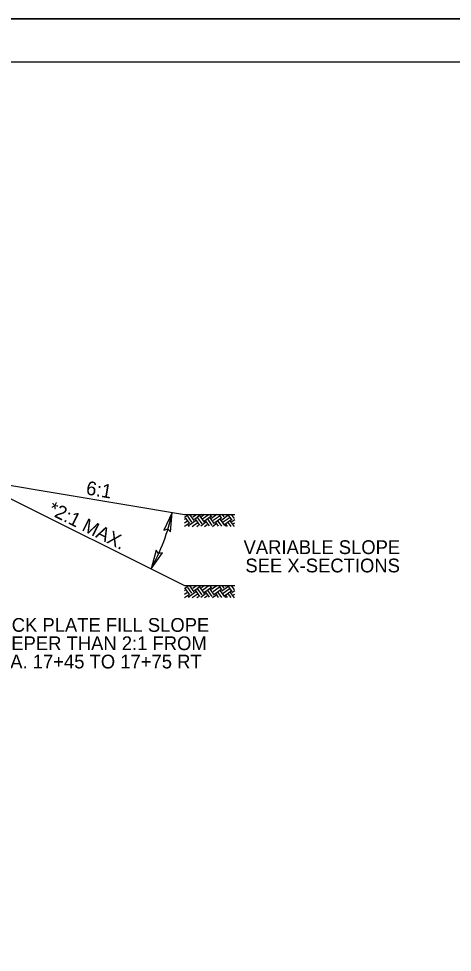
# Model space of a CAD drawing. Extents: x 1184121 to 1184397, y 1246506 to 1246661.
# Drawn here: x 1184249.3 to 1184280.8, y 1246592.7 to 1246660.5 of the extents above; entities that cross this region are included whole.
import ezdxf

# ---------------------------------------------------------------- set-up
doc = ezdxf.new("R2010")
doc.units = 0
for name, color, linetype in [('Sheet Data Field CELL', 7, 'Continuous'), ('Sheet Plan CELL', 7, 'Continuous'), ('Sheet Plot Border Outside CELL', 7, 'Continuous'), ('z - Construction', 7, 'Continuous')]:
    doc.layers.add(name, color=color, linetype=linetype)

msp = doc.modelspace()

# ---------------------------------------------------------------- linework, layer by layer
at = {"layer": 'Sheet Data Field CELL'}
for p, q in [((1184245.788, 1246627.123), (1184261.307, 1246624.537)), ((1184245.788, 1246627.123), (1184261.307, 1246619.364)), ((1184261.307, 1246624.537), (1184264.961, 1246624.537)), ((1184261.307, 1246624.537), (1184264.961, 1246624.537)), ((1184261.321, 1246624.325), (1184261.616, 1246624.537)), ((1184261.321, 1246624.325), (1184261.616, 1246624.537)), ((1184261.805, 1246624.51), (1184261.844, 1246624.538)), ((1184261.805, 1246624.51), (1184261.844, 1246624.538)), ((1184261.921, 1246624.349), (1184262.185, 1246624.539)), ((1184261.921, 1246624.349), (1184262.185, 1246624.539)), ((1184262.559, 1246624.482), (1184262.517, 1246624.54)), ((1184262.559, 1246624.482), (1184262.517, 1246624.54)), ((1184262.543, 1246624.389), (1184262.754, 1246624.541)), ((1184262.543, 1246624.389), (1184262.754, 1246624.541)), ((1184262.659, 1246624.228), (1184263.089, 1246624.537)), ((1184262.659, 1246624.228), (1184263.089, 1246624.537)), ((1184263.297, 1246624.361), (1184263.167, 1246624.542)), ((1184263.297, 1246624.361), (1184263.167, 1246624.542)), ((1184263.282, 1246624.268), (1184263.664, 1246624.543)), ((1184263.282, 1246624.268), (1184263.664, 1246624.543)), ((1184263.458, 1246624.476), (1184263.411, 1246624.542)), ((1184263.458, 1246624.476), (1184263.411, 1246624.542)), ((1184264.035, 1246624.24), (1184263.822, 1246624.537)), ((1184264.035, 1246624.24), (1184263.822, 1246624.537)), ((1184264.197, 1246624.356), (1184264.061, 1246624.544)), ((1184264.197, 1246624.356), (1184264.061, 1246624.544)), ((1184264.358, 1246624.471), (1184264.311, 1246624.537)), ((1184264.358, 1246624.471), (1184264.311, 1246624.537)), ((1184264.774, 1246624.119), (1184264.474, 1246624.537)), ((1184264.774, 1246624.119), (1184264.474, 1246624.537)), ((1184264.935, 1246624.235), (1184264.718, 1246624.537)), ((1184264.935, 1246624.235), (1184264.718, 1246624.537)), ((1184261.321, 1246624.162), (1184261.375, 1246624.201)), ((1184261.321, 1246624.162), (1184261.375, 1246624.201)), ((1184261.321, 1246623.918), (1184261.491, 1246624.04)), ((1184261.321, 1246623.918), (1184261.491, 1246624.04)), ((1184261.321, 1246623.673), (1184261.607, 1246623.879)), ((1184261.321, 1246623.673), (1184261.607, 1246623.879)), ((1184261.699, 1246623.864), (1184261.39, 1246624.294)), ((1184261.699, 1246623.864), (1184261.39, 1246624.294)), ((1184261.86, 1246623.98), (1184261.552, 1246624.409)), ((1184261.86, 1246623.98), (1184261.552, 1246624.409)), ((1184261.684, 1246623.772), (1184262.114, 1246624.08)), ((1184261.684, 1246623.772), (1184262.114, 1246624.08)), ((1184262.022, 1246624.096), (1184261.713, 1246624.525)), ((1184262.022, 1246624.096), (1184261.713, 1246624.525)), ((1184261.872, 1246623.662), (1184262.23, 1246623.919)), ((1184261.872, 1246623.662), (1184262.23, 1246623.919)), ((1184262.037, 1246624.188), (1184262.466, 1246624.497)), ((1184262.037, 1246624.188), (1184262.466, 1246624.497)), ((1184262.438, 1246623.743), (1184262.129, 1246624.173)), ((1184262.438, 1246623.743), (1184262.129, 1246624.173)), ((1184262.599, 1246623.859), (1184262.29, 1246624.289)), ((1184262.599, 1246623.859), (1184262.29, 1246624.289)), ((1184262.76, 1246623.975), (1184262.451, 1246624.404)), ((1184262.76, 1246623.975), (1184262.451, 1246624.404)), ((1184262.499, 1246623.706), (1184262.852, 1246623.96)), ((1184262.499, 1246623.706), (1184262.852, 1246623.96)), ((1184262.775, 1246624.067), (1184263.205, 1246624.376)), ((1184262.775, 1246624.067), (1184263.205, 1246624.376)), ((1184263.125, 1246623.693), (1184262.867, 1246624.052)), ((1184263.125, 1246623.693), (1184262.867, 1246624.052)), ((1184263.337, 1246623.738), (1184263.028, 1246624.168)), ((1184263.337, 1246623.738), (1184263.028, 1246624.168)), ((1184263.498, 1246623.854), (1184263.19, 1246624.283)), ((1184263.498, 1246623.854), (1184263.19, 1246624.283)), ((1184263.398, 1246624.107), (1184263.827, 1246624.416)), ((1184263.398, 1246624.107), (1184263.827, 1246624.416)), ((1184263.513, 1246623.946), (1184263.943, 1246624.255)), ((1184263.513, 1246623.946), (1184263.943, 1246624.255)), ((1184263.786, 1246623.68), (1184263.606, 1246623.931)), ((1184263.786, 1246623.68), (1184263.606, 1246623.931)), ((1184264.034, 1246623.675), (1184263.767, 1246624.047)), ((1184264.034, 1246623.675), (1184263.767, 1246624.047)), ((1184264.237, 1246623.733), (1184263.928, 1246624.163)), ((1184264.237, 1246623.733), (1184263.928, 1246624.163)), ((1184264.02, 1246624.147), (1184264.45, 1246624.456)), ((1184264.02, 1246624.147), (1184264.45, 1246624.456)), ((1184264.136, 1246623.986), (1184264.566, 1246624.295)), ((1184264.136, 1246623.986), (1184264.566, 1246624.295)), ((1184264.252, 1246623.825), (1184264.682, 1246624.134)), ((1184264.252, 1246623.825), (1184264.682, 1246624.134)), ((1184264.695, 1246623.662), (1184264.505, 1246623.926)), ((1184264.695, 1246623.662), (1184264.505, 1246623.926)), ((1184264.943, 1246623.657), (1184264.666, 1246624.042)), ((1184264.943, 1246623.657), (1184264.666, 1246624.042)), ((1184264.759, 1246624.027), (1184264.961, 1246624.172)), ((1184264.759, 1246624.027), (1184264.961, 1246624.172)), ((1184264.874, 1246623.865), (1184264.961, 1246623.927)), ((1184264.874, 1246623.865), (1184264.961, 1246623.927)), ((1184261.681, 1246623.662), (1184261.592, 1246623.787)), ((1184261.681, 1246623.662), (1184261.592, 1246623.787)), ((1184262.212, 1246623.662), (1184262.345, 1246623.758)), ((1184262.212, 1246623.662), (1184262.345, 1246623.758)), ((1184262.779, 1246623.662), (1184262.968, 1246623.798)), ((1184262.779, 1246623.662), (1184262.968, 1246623.798)), ((1184263.345, 1246623.662), (1184263.591, 1246623.839)), ((1184263.345, 1246623.662), (1184263.591, 1246623.839)), ((1184264.263, 1246623.671), (1184264.329, 1246623.718)), ((1184264.263, 1246623.671), (1184264.329, 1246623.718)), ((1184264.447, 1246623.667), (1184264.344, 1246623.81)), ((1184264.447, 1246623.667), (1184264.344, 1246623.81)), ((1184261.307, 1246619.364), (1184264.961, 1246619.364)), ((1184261.307, 1246619.364), (1184264.961, 1246619.364)), ((1184261.321, 1246619.152), (1184261.616, 1246619.364)), ((1184261.321, 1246619.152), (1184261.616, 1246619.364)), ((1184261.699, 1246618.691), (1184261.39, 1246619.121)), ((1184261.699, 1246618.691), (1184261.39, 1246619.121)), ((1184261.86, 1246618.807), (1184261.552, 1246619.236)), ((1184261.86, 1246618.807), (1184261.552, 1246619.236)), ((1184262.022, 1246618.923), (1184261.713, 1246619.352)), ((1184262.022, 1246618.923), (1184261.713, 1246619.352)), ((1184261.805, 1246619.337), (1184261.844, 1246619.365)), ((1184261.805, 1246619.337), (1184261.844, 1246619.365)), ((1184261.921, 1246619.176), (1184262.185, 1246619.366)), ((1184261.921, 1246619.176), (1184262.185, 1246619.366)), ((1184262.037, 1246619.015), (1184262.466, 1246619.324)), ((1184262.037, 1246619.015), (1184262.466, 1246619.324)), ((1184262.599, 1246618.686), (1184262.29, 1246619.116)), ((1184262.599, 1246618.686), (1184262.29, 1246619.116)), ((1184262.76, 1246618.802), (1184262.451, 1246619.231)), ((1184262.76, 1246618.802), (1184262.451, 1246619.231)), ((1184262.559, 1246619.308), (1184262.517, 1246619.367)), ((1184262.559, 1246619.308), (1184262.517, 1246619.367)), ((1184262.543, 1246619.216), (1184262.754, 1246619.368)), ((1184262.543, 1246619.216), (1184262.754, 1246619.368)), ((1184262.659, 1246619.055), (1184263.089, 1246619.364)), ((1184262.659, 1246619.055), (1184263.089, 1246619.364)), ((1184262.775, 1246618.894), (1184263.205, 1246619.203)), ((1184262.775, 1246618.894), (1184263.205, 1246619.203)), ((1184263.297, 1246619.188), (1184263.167, 1246619.369)), ((1184263.297, 1246619.188), (1184263.167, 1246619.369)), ((1184263.282, 1246619.095), (1184263.664, 1246619.37)), ((1184263.282, 1246619.095), (1184263.664, 1246619.37)), ((1184263.398, 1246618.934), (1184263.827, 1246619.243)), ((1184263.398, 1246618.934), (1184263.827, 1246619.243)), ((1184263.458, 1246619.303), (1184263.411, 1246619.369)), ((1184263.458, 1246619.303), (1184263.411, 1246619.369)), ((1184264.035, 1246619.067), (1184263.822, 1246619.364)), ((1184264.035, 1246619.067), (1184263.822, 1246619.364)), ((1184264.02, 1246618.974), (1184264.45, 1246619.283)), ((1184264.02, 1246618.974), (1184264.45, 1246619.283)), ((1184264.197, 1246619.183), (1184264.061, 1246619.371)), ((1184264.197, 1246619.183), (1184264.061, 1246619.371)), ((1184264.136, 1246618.813), (1184264.566, 1246619.122)), ((1184264.136, 1246618.813), (1184264.566, 1246619.122)), ((1184264.358, 1246619.298), (1184264.311, 1246619.364)), ((1184264.358, 1246619.298), (1184264.311, 1246619.364)), ((1184264.774, 1246618.946), (1184264.474, 1246619.364)), ((1184264.774, 1246618.946), (1184264.474, 1246619.364)), ((1184264.935, 1246619.062), (1184264.718, 1246619.364)), ((1184264.935, 1246619.062), (1184264.718, 1246619.364)), ((1184261.321, 1246618.989), (1184261.375, 1246619.028)), ((1184261.321, 1246618.989), (1184261.375, 1246619.028)), ((1184261.321, 1246618.745), (1184261.491, 1246618.867)), ((1184261.321, 1246618.745), (1184261.491, 1246618.867)), ((1184261.321, 1246618.5), (1184261.607, 1246618.706)), ((1184261.321, 1246618.5), (1184261.607, 1246618.706)), ((1184261.681, 1246618.489), (1184261.592, 1246618.614)), ((1184261.681, 1246618.489), (1184261.592, 1246618.614)), ((1184261.684, 1246618.599), (1184262.114, 1246618.907)), ((1184261.684, 1246618.599), (1184262.114, 1246618.907)), ((1184261.872, 1246618.489), (1184262.23, 1246618.746)), ((1184261.872, 1246618.489), (1184262.23, 1246618.746)), ((1184262.438, 1246618.57), (1184262.129, 1246619)), ((1184262.438, 1246618.57), (1184262.129, 1246619)), ((1184262.212, 1246618.489), (1184262.345, 1246618.585)), ((1184262.212, 1246618.489), (1184262.345, 1246618.585)), ((1184262.499, 1246618.533), (1184262.852, 1246618.787)), ((1184262.499, 1246618.533), (1184262.852, 1246618.787)), ((1184262.779, 1246618.489), (1184262.968, 1246618.625)), ((1184262.779, 1246618.489), (1184262.968, 1246618.625)), ((1184263.125, 1246618.52), (1184262.867, 1246618.879)), ((1184263.125, 1246618.52), (1184262.867, 1246618.879)), ((1184263.337, 1246618.565), (1184263.028, 1246618.995)), ((1184263.337, 1246618.565), (1184263.028, 1246618.995)), ((1184263.498, 1246618.681), (1184263.19, 1246619.11)), ((1184263.498, 1246618.681), (1184263.19, 1246619.11)), ((1184263.345, 1246618.489), (1184263.591, 1246618.666)), ((1184263.345, 1246618.489), (1184263.591, 1246618.666)), ((1184263.513, 1246618.773), (1184263.943, 1246619.082)), ((1184263.513, 1246618.773), (1184263.943, 1246619.082)), ((1184263.786, 1246618.507), (1184263.606, 1246618.758)), ((1184263.786, 1246618.507), (1184263.606, 1246618.758)), ((1184264.034, 1246618.502), (1184263.767, 1246618.874)), ((1184264.034, 1246618.502), (1184263.767, 1246618.874)), ((1184264.237, 1246618.56), (1184263.928, 1246618.99)), ((1184264.237, 1246618.56), (1184263.928, 1246618.99)), ((1184264.252, 1246618.652), (1184264.682, 1246618.961)), ((1184264.252, 1246618.652), (1184264.682, 1246618.961)), ((1184264.263, 1246618.498), (1184264.329, 1246618.545)), ((1184264.263, 1246618.498), (1184264.329, 1246618.545)), ((1184264.447, 1246618.494), (1184264.344, 1246618.637)), ((1184264.447, 1246618.494), (1184264.344, 1246618.637)), ((1184264.695, 1246618.489), (1184264.505, 1246618.753)), ((1184264.695, 1246618.489), (1184264.505, 1246618.753)), ((1184264.943, 1246618.484), (1184264.666, 1246618.869)), ((1184264.943, 1246618.484), (1184264.666, 1246618.869)), ((1184264.759, 1246618.854), (1184264.961, 1246618.999)), ((1184264.759, 1246618.854), (1184264.961, 1246618.999)), ((1184264.874, 1246618.692), (1184264.961, 1246618.754)), ((1184264.874, 1246618.692), (1184264.961, 1246618.754))]:
    msp.add_line(p, q, dxfattribs=at)
for points in [[(1184260.298, 1246623.262), (1184260.432, 1246624.683), (1184259.821, 1246623.383), (1184260.109, 1246623.491)], [(1184259.271, 1246621.947), (1184258.89, 1246620.572), (1184259.719, 1246621.744), (1184259.417, 1246621.688)]]:
    msp.add_lwpolyline(points, close=True, dxfattribs=at)
msp.add_arc((1184245.768, 1246627.84), 15, 331.01715, 347.8465, dxfattribs=at)
at = {"layer": 'Sheet Plan CELL'}
msp.add_line((1184358.423, 1246657.364), (1184126.184, 1246657.364), dxfattribs=at)
at = {"layer": 'Sheet Plot Border Outside CELL'}
msp.add_lwpolyline([(1184121.05, 1246660.53), (1184360.324, 1246660.53), (1184360.324, 1246505.708), (1184121.05, 1246505.708)], close=True, dxfattribs=at)
at = {"layer": 'z - Construction'}
msp.add_line((1184360.324, 1246660.53), (1184121.05, 1246660.53), dxfattribs=at)

# ---------------------------------------------------------------- texts
at = {"layer": 'Sheet Data Field CELL'}
for s, rotation, p in [('6:1', 350.53748, (1184254.118, 1246625.988)), ('*2:1 MAX.', 333.43475, (1184251.339, 1246624.627)), ('VARIABLE SLOPE', 360, (1184265.605, 1246621.655)), ('SEE X-SECTIONS', 360, (1184265.738, 1246620.325)), ('*ROCK PLATE FILL SLOPE', 360, (1184246.245, 1246616.008)), ('STEEPER THAN 2:1 FROM', 360, (1184246.139, 1246614.678)), ('-L- STA. 17+45 TO 17+75 RT', 360, (1184244.948, 1246613.348))]:
    msp.add_text(s, height=1, rotation=rotation, dxfattribs=at).set_placement(p)

doc.saveas('drawing.dxf')
